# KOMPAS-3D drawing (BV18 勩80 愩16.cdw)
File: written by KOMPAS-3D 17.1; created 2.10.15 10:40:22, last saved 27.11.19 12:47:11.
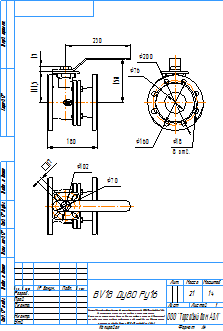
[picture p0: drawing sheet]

Sheet 1: A4, portrait

Title block, sheet 1: name: BV18 Ду80 Ру16; material: Сталь 10  ГОСТ 1050-88; mass: 21; sheets: 1; sheet format: A4; stored path: C:\Users\kka\KOMPAS_Work\!Trash\BV18\KOMPAS 2D\BV18 Ду100 Ру16 с голым штоком.cdw

Views: Спереди 4, Проекционный вид 5, Проекционный вид 6
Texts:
  Klimkovich
  ADL
  Рама для чертежей
  Лит-Масса-Масштаб
  Материал-Предприятие
  Масштаб
  Изм.
  Лист
  № докум.
  Подп.
  Дата
  Лит.
  Разраб.
  Пров.
  Т.контр.
  Листов
  Внимание! Данный продукт является объектом авторского права ООО «Торговый Дом АДЛ».
  Запрещается изменение, копирование, распространение
  (в том числе путем копирования на другие сайты и ресурсы в Интернете)
  или любое иное использование информации и объектов без предварительного
  согласия правообладателя (ООО «Торговый Дом АДЛ»).
  Н.контр.
  Утв.
  ООО "Торговый дом АДЛ"
  Изменение
  Номер документа
  Подпись
  Обозначение документа
  Наименование изделия
  Масса изделия по ГОСТ 2.109-73
  Порядковый номер листа
  Общее количество листов в документе
  Характер работы, выполненной лицом, подписавшим документ
  Наименование или индекс предприятия, выпускающего документ
  Инв. № подл.
  Подп. и дата
  Взам. инв. №
  Инв. № дубл.
  Инвентарный номер подлинника по ГОСТ 2.501-68
  Подпись принявшего подлинник в отдел технической документации
  Инвентарный номер подлинника, взамен которого выпущен данный подлинник
  Инвентарный номер дубликата по ГОСТ 2.502-68
  Подпись принявшего дубликат в отдел технической документации
  Справ. №
  Перв. примен.
  Обозначение документа, взамен или на основании которого выпущен данный документ
  Обозначение документа, в котором впервые записан данный документ
  Подпись лица, копировавшего чертеж
  Обозначение формата листа
  !Рама для чертежа
Dimensions and other numbers on the sheet: 111,5; 17; 180; 230; 158; 102; 70; 200; 160; 18; 8 отв.; 76; 1:4; 1; 21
